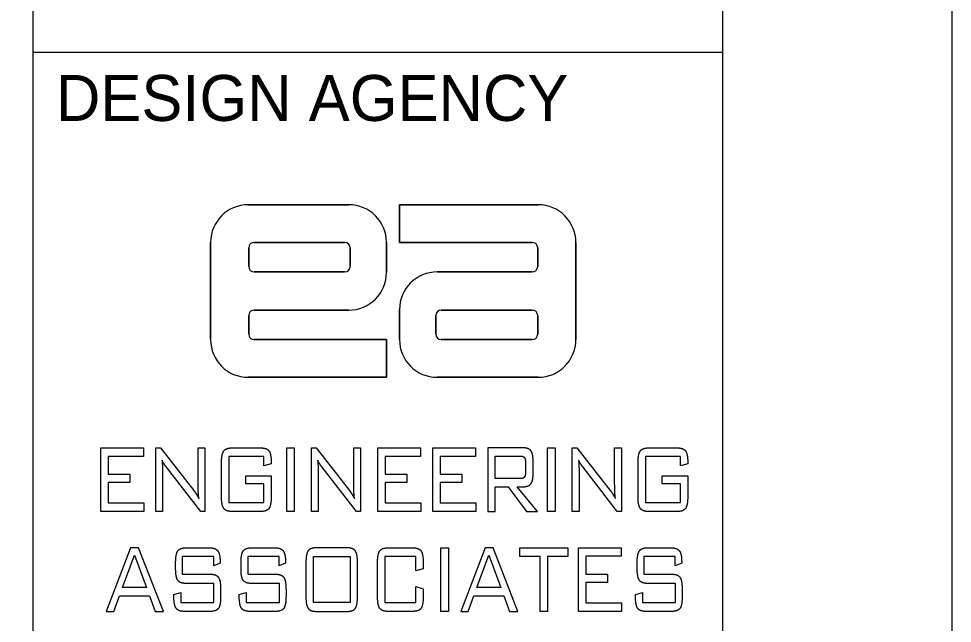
# Model space of a CAD drawing. Extents: x 0 to 34, y -0.8 to 22.
# Drawn here: x 31.969 to 34, y 3.757 to 5.073 of the extents above; entities that cross this region are included whole.
import ezdxf

# ---------------------------------------------------------------- set-up
doc = ezdxf.new("R2010")
doc.units = 0
for name, color, linetype in [('SH_Border', 7, 'Continuous'), ('SH_Cut_Line', 7, 'Continuous'), ('SH_Data', 7, 'Continuous'), ('TX_X_20', 7, 'Continuous')]:
    doc.layers.add(name, color=color, linetype=linetype)

msp = doc.modelspace()

# ---------------------------------------------------------------- linework, layer by layer
at = {"layer": 'SH_Border'}
for p, q in [((32, 0.5), (32, 21.5)), ((32, 5), (33.5, 5))]:
    msp.add_line(p, q, dxfattribs=at)
msp.add_lwpolyline([(1.5, 21.5), (33.5, 21.5), (33.5, 0.5), (1.5, 0.5)], close=True, dxfattribs=at)
at = {"layer": 'SH_Cut_Line'}
msp.add_lwpolyline([(0, 0), (34, 0), (34, 22), (0, 22)], close=True, dxfattribs=at)
at = {"layer": 'SH_Data'}
msp.add_line((32.75, 4), (32.75, 4), dxfattribs=at)
at = {"layer": 'TX_X_20'}
for p, q in [((32.6869, 4.6677), (32.4684, 4.6677)), ((32.4684, 4.6677), (32.6869, 4.6677)), ((32.7974, 4.6677), (33.0989, 4.6677)), ((32.7974, 4.5856), (32.7974, 4.6677)), ((32.3863, 4.5856), (32.3863, 4.3741)), ((32.3863, 4.3741), (32.3863, 4.5856)), ((32.4694, 4.5332), (32.4694, 4.5738)), ((32.4694, 4.5738), (32.4694, 4.5332)), ((32.4812, 4.5856), (32.678, 4.5856)), ((32.678, 4.5856), (32.4812, 4.5856)), ((32.6898, 4.5738), (32.6898, 4.5332)), ((32.6898, 4.5332), (32.6898, 4.5738)), ((32.7689, 4.5204), (32.7689, 4.5856)), ((32.7689, 4.5856), (32.7689, 4.5204)), ((33.086, 4.5856), (32.7974, 4.5856)), ((33.0979, 4.5738), (33.0979, 4.5332)), ((33.0979, 4.5332), (33.0979, 4.5738)), ((33.1809, 4.3741), (33.1809, 4.5856)), ((33.1809, 4.5856), (33.1809, 4.3741)), ((32.678, 4.5214), (32.4812, 4.5214)), ((32.4812, 4.5214), (32.678, 4.5214)), ((33.086, 4.5214), (32.8794, 4.5214)), ((32.8794, 4.5214), (33.086, 4.5214)), ((32.4812, 4.4383), (32.6869, 4.4383)), ((32.6869, 4.4383), (32.4812, 4.4383)), ((32.7974, 4.4393), (32.7974, 4.3741)), ((32.7974, 4.3741), (32.7974, 4.4393)), ((32.8883, 4.4383), (33.086, 4.4383)), ((33.086, 4.4383), (32.8883, 4.4383)), ((32.4694, 4.3859), (32.4694, 4.4265)), ((32.4694, 4.4265), (32.4694, 4.3859)), ((32.8765, 4.3859), (32.8765, 4.4265)), ((32.8765, 4.4265), (32.8765, 4.3859)), ((33.0979, 4.4265), (33.0979, 4.3859)), ((33.0979, 4.3859), (33.0979, 4.4265)), ((32.4812, 4.3741), (32.7689, 4.3741)), ((32.7689, 4.3741), (32.7689, 4.292)), ((33.086, 4.3741), (32.8883, 4.3741)), ((32.8883, 4.3741), (33.086, 4.3741)), ((32.7689, 4.292), (32.4684, 4.292)), ((32.8794, 4.292), (33.0989, 4.292)), ((33.0989, 4.292), (32.8794, 4.292)), ((32.4329, 4.1384), (32.4956, 4.1384)), ((33.339, 4.1384), (33.4017, 4.1384)), ((32.4101, 4.0328), (32.4101, 4.1057)), ((33.0715, 4.1062), (33.0715, 4.086)), ((33.0879, 4.0806), (33.0879, 4.1116)), ((33.3163, 4.0328), (33.3163, 4.1057)), ((32.4956, 4), (32.4329, 4)), ((33.4017, 4), (33.339, 4)), ((32.3328, 3.9209), (32.3843, 3.9209)), ((32.475, 3.9209), (32.5265, 3.9209)), ((32.6834, 3.9209), (32.6165, 3.9209)), ((32.7722, 3.9209), (32.8264, 3.9209)), ((33.3369, 3.9209), (33.3884, 3.9209)), ((32.3103, 3.8761), (32.3103, 3.8882)), ((32.4525, 3.8761), (32.4525, 3.8882)), ((32.5937, 3.8882), (32.5937, 3.8152)), ((32.706, 3.8152), (32.706, 3.8882)), ((32.7495, 3.8152), (32.7495, 3.8882)), ((33.3144, 3.8761), (33.3144, 3.8882)), ((32.4082, 3.8308), (32.4082, 3.8152)), ((32.5504, 3.8308), (32.5504, 3.8152)), ((33.4123, 3.8308), (33.4123, 3.8152)), ((32.3857, 3.7825), (32.3293, 3.7825)), ((32.5279, 3.7825), (32.4715, 3.7825)), ((32.6165, 3.7825), (32.6834, 3.7825)), ((32.8264, 3.7825), (32.7722, 3.7825)), ((33.3898, 3.7825), (33.3334, 3.7825))]:
    msp.add_line(p, q, dxfattribs=at)
for points in [[(33.0989, 4.6677), (32.7974, 4.6677), (32.7974, 4.5856), (33.086, 4.5856)], [(32.4684, 4.292), (32.7689, 4.292), (32.7689, 4.3741), (32.4812, 4.3741)], [(32.2819, 4.0816), (32.2819, 4), (32.2671, 4), (32.2671, 4.1384), (32.2773, 4.1384), (32.3497, 4.0458)], [(32.3593, 4.0625), (32.3593, 4.1384), (32.3741, 4.1384), (32.3741, 4), (32.365, 4), (32.2906, 4.0962)], [(32.6204, 4.0816), (32.6204, 4), (32.6056, 4), (32.6056, 4.1384), (32.6158, 4.1384), (32.6883, 4.0458)], [(32.6978, 4.0625), (32.6978, 4.1384), (32.7126, 4.1384), (32.7126, 4), (32.7035, 4), (32.6291, 4.0962)], [(33.0674, 4.1384), (32.9893, 4.1384), (32.9893, 4), (33.0056, 4), (33.0056, 4.0539), (33.034, 4.0539), (33.0734, 4), (33.0974, 4), (33.0532, 4.0539), (33.0674, 4.0539)], [(33.188, 4.0816), (33.188, 4), (33.1732, 4), (33.1732, 4.1384), (33.1834, 4.1384), (33.2559, 4.0458)], [(33.2654, 4.0625), (33.2654, 4.1384), (33.2802, 4.1384), (33.2802, 4), (33.2711, 4), (33.1967, 4.0962)], [(32.5183, 4.1072), (32.5183, 4.1038), (32.5022, 4.0992), (32.5022, 4.1196), (32.4263, 4.1196), (32.4263, 4.0192), (32.5022, 4.0192), (32.5022, 4.0599), (32.463, 4.0599), (32.463, 4.0775), (32.5183, 4.0775), (32.5183, 4.0328)], [(33.061, 4.0718), (33.0056, 4.0718), (33.0056, 4.1205), (33.061, 4.1205)], [(33.4244, 4.1072), (33.4244, 4.1038), (33.4083, 4.0992), (33.4083, 4.1196), (33.3324, 4.1196), (33.3324, 4.0192), (33.4083, 4.0192), (33.4083, 4.0599), (33.3691, 4.0599), (33.3691, 4.0775), (33.4244, 4.0775), (33.4244, 4.0328)], [(32.407, 3.8905), (32.407, 3.8877), (32.3932, 3.882), (32.3932, 3.9021), (32.3248, 3.9021), (32.3248, 3.8635), (32.3857, 3.8635)], [(32.5493, 3.8905), (32.5493, 3.8877), (32.5354, 3.882), (32.5354, 3.9021), (32.467, 3.9021), (32.467, 3.8635), (32.5279, 3.8635)], [(32.849, 3.8882), (32.849, 3.8751), (32.8327, 3.8708), (32.8327, 3.9021), (32.7656, 3.9021), (32.7656, 3.8018), (32.8327, 3.8018), (32.8327, 3.8364), (32.849, 3.8316), (32.849, 3.8152)], [(33.4112, 3.8905), (33.4112, 3.8877), (33.3973, 3.882), (33.3973, 3.9021), (33.3289, 3.9021), (33.3289, 3.8635), (33.3898, 3.8635)], [(32.3065, 3.8152), (32.3065, 3.819), (32.3215, 3.824), (32.3215, 3.8018), (32.3937, 3.8018), (32.3937, 3.8434), (32.3328, 3.8434)], [(32.4487, 3.8152), (32.4487, 3.819), (32.4637, 3.824), (32.4637, 3.8018), (32.5359, 3.8018), (32.5359, 3.8434), (32.475, 3.8434)], [(33.3107, 3.8152), (33.3107, 3.819), (33.3257, 3.824), (33.3257, 3.8018), (33.3978, 3.8018), (33.3978, 3.8434), (33.3369, 3.8434)]]:
    msp.add_lwpolyline(points, dxfattribs=at)
for points in [[(32.1474, 4), (32.1474, 4.1384), (32.2407, 4.1384), (32.2407, 4.1198), (32.1637, 4.1198), (32.1637, 4.0813), (32.2108, 4.0813), (32.2108, 4.0631), (32.1637, 4.0631), (32.1637, 4.019), (32.2414, 4.019), (32.2414, 4)], [(32.552, 4), (32.552, 4.1384), (32.5682, 4.1384), (32.5682, 4)], [(32.75, 4), (32.75, 4.1384), (32.8433, 4.1384), (32.8433, 4.1198), (32.7662, 4.1198), (32.7662, 4.0813), (32.8133, 4.0813), (32.8133, 4.0631), (32.7662, 4.0631), (32.7662, 4.019), (32.844, 4.019), (32.844, 4)], [(32.8697, 4), (32.8697, 4.1384), (32.9629, 4.1384), (32.9629, 4.1198), (32.8859, 4.1198), (32.8859, 4.0813), (32.933, 4.0813), (32.933, 4.0631), (32.8859, 4.0631), (32.8859, 4.019), (32.9637, 4.019), (32.9637, 4)], [(33.1196, 4), (33.1196, 4.1384), (33.1358, 4.1384), (33.1358, 4)], [(32.1595, 3.7825), (32.1755, 3.7825), (32.1879, 3.8166), (32.2534, 3.8166), (32.2658, 3.7825), (32.2836, 3.7825), (32.2297, 3.9209), (32.2124, 3.9209)], [(32.8873, 3.7825), (32.8873, 3.9209), (32.9036, 3.9209), (32.9036, 3.7825)], [(32.9305, 3.7825), (32.9465, 3.7825), (32.9589, 3.8166), (33.0244, 3.8166), (33.0368, 3.7825), (33.0546, 3.7825), (33.0008, 3.9209), (32.9834, 3.9209)], [(33.1192, 3.9021), (33.1192, 3.7825), (33.103, 3.7825), (33.103, 3.9021), (33.0588, 3.9021), (33.0588, 3.9209), (33.1636, 3.9209), (33.1636, 3.9021)], [(33.1866, 3.7825), (33.1866, 3.9209), (33.2798, 3.9209), (33.2798, 3.9024), (33.2028, 3.9024), (33.2028, 3.8639), (33.2499, 3.8639), (33.2499, 3.8456), (33.2028, 3.8456), (33.2028, 3.8015), (33.2806, 3.8015), (33.2806, 3.7825)], [(32.1946, 3.8342), (32.2207, 3.9051), (32.2468, 3.8342)], [(32.6099, 3.8018), (32.6099, 3.9021), (32.69, 3.9021), (32.69, 3.8018)], [(32.9657, 3.8342), (32.9917, 3.9051), (33.0178, 3.8342)]]:
    msp.add_lwpolyline(points, close=True, dxfattribs=at)
for centre, radius, start, end in [((32.4684, 4.5856), 0.0821, 90, 180), ((32.4684, 4.5856), 0.0821, 90, 180), ((32.6869, 4.5856), 0.0821, 0, 90), ((32.6869, 4.5856), 0.0821, 0, 90), ((33.0989, 4.5856), 0.0821, 0, 90), ((33.0989, 4.5856), 0.0821, 0, 90), ((32.4812, 4.5738), 0.0119, 90, 180), ((32.4812, 4.5738), 0.0119, 90, 180), ((32.678, 4.5738), 0.0119, 0, 90), ((32.678, 4.5738), 0.0119, 0, 90), ((33.086, 4.5738), 0.0119, 0, 90), ((33.086, 4.5738), 0.0119, 0, 90), ((32.4812, 4.5332), 0.0119, 180, 270), ((32.4812, 4.5332), 0.0119, 180, 270), ((32.678, 4.5332), 0.0119, 270, 0), ((32.678, 4.5332), 0.0119, 270, 0), ((33.086, 4.5332), 0.0119, 270, 0), ((33.086, 4.5332), 0.0119, 270, 0), ((32.6869, 4.5204), 0.0821, 270, 360), ((32.6869, 4.5204), 0.0821, 270, 360), ((32.8794, 4.4393), 0.0821, 90, 180), ((32.8794, 4.4393), 0.0821, 90, 180), ((32.4812, 4.4265), 0.0119, 90, 180), ((32.4812, 4.4265), 0.0119, 90, 180), ((32.8883, 4.4265), 0.0119, 90, 180), ((32.8883, 4.4265), 0.0119, 90, 180), ((33.086, 4.4265), 0.0119, 0, 90), ((33.086, 4.4265), 0.0119, 0, 90), ((32.4684, 4.3741), 0.0821, 180, 270), ((32.4684, 4.3741), 0.0821, 180, 270), ((32.4812, 4.3859), 0.0119, 180, 270), ((32.4812, 4.3859), 0.0119, 180, 270), ((32.8794, 4.3741), 0.0821, 180, 270), ((32.8794, 4.3741), 0.0821, 180, 270), ((32.8883, 4.3859), 0.0119, 180, 270), ((32.8883, 4.3859), 0.0119, 180, 270), ((33.086, 4.3859), 0.0119, 270, 0), ((33.086, 4.3859), 0.0119, 270, 0), ((33.0989, 4.3741), 0.0821, 270, 360), ((33.0989, 4.3741), 0.0821, 270, 360)]:
    msp.add_arc(centre, radius, start, end, dxfattribs=at)
for points in [[(32.4101, 4.1057), (32.4101, 4.1245), (32.4149, 4.1315)], [(32.4149, 4.1315), (32.4196, 4.1384), (32.4329, 4.1384)], [(32.4956, 4.1384), (32.5086, 4.1384), (32.5134, 4.1317)], [(32.5134, 4.1317), (32.5183, 4.1249), (32.5183, 4.1072)], [(33.0831, 4.1321), (33.0783, 4.1384), (33.0674, 4.1384)], [(33.0879, 4.1116), (33.0879, 4.1257), (33.0831, 4.1321)], [(33.3163, 4.1057), (33.3163, 4.1245), (33.321, 4.1315)], [(33.321, 4.1315), (33.3257, 4.1384), (33.339, 4.1384)], [(33.4017, 4.1384), (33.4147, 4.1384), (33.4196, 4.1317)], [(33.4196, 4.1317), (33.4244, 4.1249), (33.4244, 4.1072)], [(32.2889, 4.0983), (32.2834, 4.1054), (32.2808, 4.1118)], [(32.2808, 4.1118), (32.2813, 4.1055), (32.2816, 4.0984)], [(32.6275, 4.0983), (32.622, 4.1054), (32.6193, 4.1118)], [(32.6193, 4.1118), (32.6199, 4.1055), (32.6201, 4.0984)], [(33.061, 4.1205), (33.067, 4.1205), (33.0692, 4.1173)], [(33.0692, 4.1173), (33.0715, 4.1141), (33.0715, 4.1062)], [(33.1951, 4.0983), (33.1896, 4.1054), (33.1869, 4.1118)], [(33.1869, 4.1118), (33.1875, 4.1055), (33.1877, 4.0984)], [(32.2816, 4.0984), (32.2819, 4.0913), (32.2819, 4.0816)], [(32.2906, 4.0962), (32.29, 4.0969), (32.2889, 4.0983)], [(32.6201, 4.0984), (32.6204, 4.0913), (32.6204, 4.0816)], [(32.6291, 4.0962), (32.6286, 4.0969), (32.6275, 4.0983)], [(33.0715, 4.086), (33.0715, 4.0781), (33.0693, 4.0749)], [(33.1877, 4.0984), (33.188, 4.0913), (33.188, 4.0816)], [(33.1967, 4.0962), (33.1962, 4.0969), (33.1951, 4.0983)], [(32.3596, 4.0424), (32.3593, 4.0496), (32.3593, 4.0625)], [(32.6982, 4.0424), (32.6978, 4.0496), (32.6978, 4.0625)], [(33.0693, 4.0749), (33.0671, 4.0718), (33.061, 4.0718)], [(33.0831, 4.0603), (33.0879, 4.0666), (33.0879, 4.0806)], [(33.2658, 4.0424), (33.2654, 4.0496), (33.2654, 4.0625)], [(32.3497, 4.0458), (32.3522, 4.0427), (32.355, 4.0382)], [(32.3607, 4.0284), (32.36, 4.0351), (32.3596, 4.0424)], [(32.6883, 4.0458), (32.6907, 4.0427), (32.6935, 4.0382)], [(32.6993, 4.0284), (32.6985, 4.0351), (32.6982, 4.0424)], [(33.0674, 4.0539), (33.0783, 4.0539), (33.0831, 4.0603)], [(33.2559, 4.0458), (33.2583, 4.0427), (33.2611, 4.0382)], [(33.2669, 4.0284), (33.2661, 4.0351), (33.2658, 4.0424)], [(32.355, 4.0382), (32.3578, 4.0338), (32.3607, 4.0284)], [(32.4149, 4.0069), (32.4101, 4.0139), (32.4101, 4.0328)], [(32.5183, 4.0328), (32.5183, 4.0138), (32.5135, 4.0069)], [(32.6935, 4.0382), (32.6963, 4.0338), (32.6993, 4.0284)], [(33.2611, 4.0382), (33.2639, 4.0338), (33.2669, 4.0284)], [(33.321, 4.0069), (33.3163, 4.0139), (33.3163, 4.0328)], [(33.4244, 4.0328), (33.4244, 4.0138), (33.4197, 4.0069)], [(32.4329, 4), (32.4196, 4), (32.4149, 4.0069)], [(32.5135, 4.0069), (32.5088, 4), (32.4956, 4)], [(33.339, 4), (33.3257, 4), (33.321, 4.0069)], [(33.4197, 4.0069), (33.4149, 4), (33.4017, 4)], [(32.3149, 3.914), (32.3196, 3.9209), (32.3328, 3.9209)], [(32.3843, 3.9209), (32.3972, 3.9209), (32.4021, 3.9142)], [(32.4571, 3.914), (32.4618, 3.9209), (32.475, 3.9209)], [(32.5265, 3.9209), (32.5394, 3.9209), (32.5443, 3.9142)], [(32.6165, 3.9209), (32.6032, 3.9209), (32.5984, 3.914)], [(32.7013, 3.914), (32.6965, 3.9209), (32.6834, 3.9209)], [(32.7543, 3.914), (32.759, 3.9209), (32.7722, 3.9209)], [(32.8264, 3.9209), (32.8396, 3.9209), (32.8443, 3.9141)], [(33.3191, 3.914), (33.3237, 3.9209), (33.3369, 3.9209)], [(33.3884, 3.9209), (33.4014, 3.9209), (33.4063, 3.9142)], [(32.3103, 3.8882), (32.3103, 3.9072), (32.3149, 3.914)], [(32.4021, 3.9142), (32.407, 3.9074), (32.407, 3.8905)], [(32.4525, 3.8882), (32.4525, 3.9072), (32.4571, 3.914)], [(32.5443, 3.9142), (32.5493, 3.9074), (32.5493, 3.8905)], [(32.5984, 3.914), (32.5937, 3.907), (32.5937, 3.8882)], [(32.706, 3.8882), (32.706, 3.9072), (32.7013, 3.914)], [(32.7495, 3.8882), (32.7495, 3.9072), (32.7543, 3.914)], [(32.8443, 3.9141), (32.849, 3.9073), (32.849, 3.8882)], [(33.3144, 3.8882), (33.3144, 3.9072), (33.3191, 3.914)], [(33.4063, 3.9142), (33.4112, 3.9074), (33.4112, 3.8905)], [(32.3149, 3.8503), (32.3103, 3.8571), (32.3103, 3.8761)], [(32.3857, 3.8635), (32.3986, 3.8635), (32.4034, 3.8566)], [(32.4571, 3.8503), (32.4525, 3.8571), (32.4525, 3.8761)], [(32.5279, 3.8635), (32.5408, 3.8635), (32.5456, 3.8566)], [(33.3191, 3.8503), (33.3144, 3.8571), (33.3144, 3.8761)], [(33.3898, 3.8635), (33.4028, 3.8635), (33.4075, 3.8566)], [(32.3328, 3.8434), (32.3196, 3.8434), (32.3149, 3.8503)], [(32.4034, 3.8566), (32.4082, 3.8498), (32.4082, 3.8308)], [(32.475, 3.8434), (32.4618, 3.8434), (32.4571, 3.8503)], [(32.5456, 3.8566), (32.5504, 3.8498), (32.5504, 3.8308)], [(33.3369, 3.8434), (33.3237, 3.8434), (33.3191, 3.8503)], [(33.4075, 3.8566), (33.4123, 3.8498), (33.4123, 3.8308)], [(32.3113, 3.7894), (32.3065, 3.7963), (32.3065, 3.8152)], [(32.4082, 3.8152), (32.4082, 3.7961), (32.4035, 3.7893)], [(32.4535, 3.7894), (32.4487, 3.7963), (32.4487, 3.8152)], [(32.5504, 3.8152), (32.5504, 3.7961), (32.5457, 3.7893)], [(32.5937, 3.8152), (32.5937, 3.7964), (32.5984, 3.7895)], [(32.7013, 3.7893), (32.706, 3.7961), (32.706, 3.8152)], [(32.7543, 3.7894), (32.7495, 3.7963), (32.7495, 3.8152)], [(32.849, 3.8152), (32.849, 3.7961), (32.8443, 3.7893)], [(33.3154, 3.7894), (33.3107, 3.7963), (33.3107, 3.8152)], [(33.4123, 3.8152), (33.4123, 3.7961), (33.4076, 3.7893)], [(32.3293, 3.7825), (32.3161, 3.7825), (32.3113, 3.7894)], [(32.4035, 3.7893), (32.3988, 3.7825), (32.3857, 3.7825)], [(32.4715, 3.7825), (32.4583, 3.7825), (32.4535, 3.7894)], [(32.5457, 3.7893), (32.541, 3.7825), (32.5279, 3.7825)], [(32.5984, 3.7895), (32.6032, 3.7825), (32.6165, 3.7825)], [(32.6834, 3.7825), (32.6965, 3.7825), (32.7013, 3.7893)], [(32.7722, 3.7825), (32.759, 3.7825), (32.7543, 3.7894)], [(32.8443, 3.7893), (32.8396, 3.7825), (32.8264, 3.7825)], [(33.3334, 3.7825), (33.3202, 3.7825), (33.3154, 3.7894)], [(33.4076, 3.7893), (33.4029, 3.7825), (33.3898, 3.7825)]]:
    msp.add_open_spline(points, degree=2, dxfattribs=at)

# ---------------------------------------------------------------- texts
at = {"layer": 'SH_Data'}
msp.add_text('DESIGN AGENCY', height=0.1, dxfattribs=at).set_placement((32.05, 4.85))

doc.saveas('drawing.dxf')
